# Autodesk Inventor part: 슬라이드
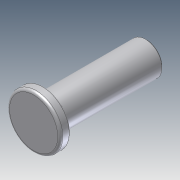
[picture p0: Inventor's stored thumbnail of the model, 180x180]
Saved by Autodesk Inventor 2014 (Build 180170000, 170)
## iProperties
Company: 한국ATC센터
Created: 2014-01
Part Number: 슬라이드
Document SubType Name: Modeling
Designer: KYOUNG IL JANG
Density: 7.86 g/cm^3
Material: 강철, 연강
Mass: 53.476 g
Surface Area: 25.6477 cm^2
Volume: 6.80356 cm^3
Vendor: CBT Solutions
Appearance: 강철
Author: KYOUNG IL JANG
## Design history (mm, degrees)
sketch "스케치1"
  geometry: L1 (13.5, 41)-(13.5, 74) reference; L2 (13.5, 74)-(26.5, 74) reference; L3 (20, 74)-(20, 29); L4 (20, 74)-(13.5, 74); L5 (13.5, 74)-(13.5, 33); L6 (13.5, 33)-(9.5, 33); L7 (9.5, 33)-(9.5, 29); L8 (20, 73.5)-(13.5, 73.5); L9 (20, 29)-(9.5, 29); 1 further point
  constraints: 16 end point, 4 perpendicular, 3 point on line, 1 collinear, 1 midpoint, 1 parallel, 1 vertical, 2 other
  dimensions: "d0" = 45 distance of L3.start L3.end; "d1" = 21 diameter of L7 L3; "d2" = 4 distance from line of L3.end L6; "d4" = 0.5 distance between parallel lines of L8 L2
revolve "회전1" sketch "스케치1" stored, may be unused: angle "d5" = 90 deg
fillet "모깎기1" dims "d6" = 1
fillet "모깎기3" dims "d8" = 0.5
chamfer "모따기1" distance "d9" = 0.5; stored, may be unused: second distance "d10" = 2, angle "d11" = 45 deg
sketch "스케치2"
  geometry: C1 r 6.5 at (0, 0) reference; C2 r 7.25 at (0, 0); 1 further point
  constraints: 1 centre point, 1 coincident
  dimensions: "d12" = 14.5 diameter of C2
extrude "돌출1" join sketch "스케치2" distance "d13" = 2; taper "d14" = 0 deg
node "솔리드1"
node "참조1"
